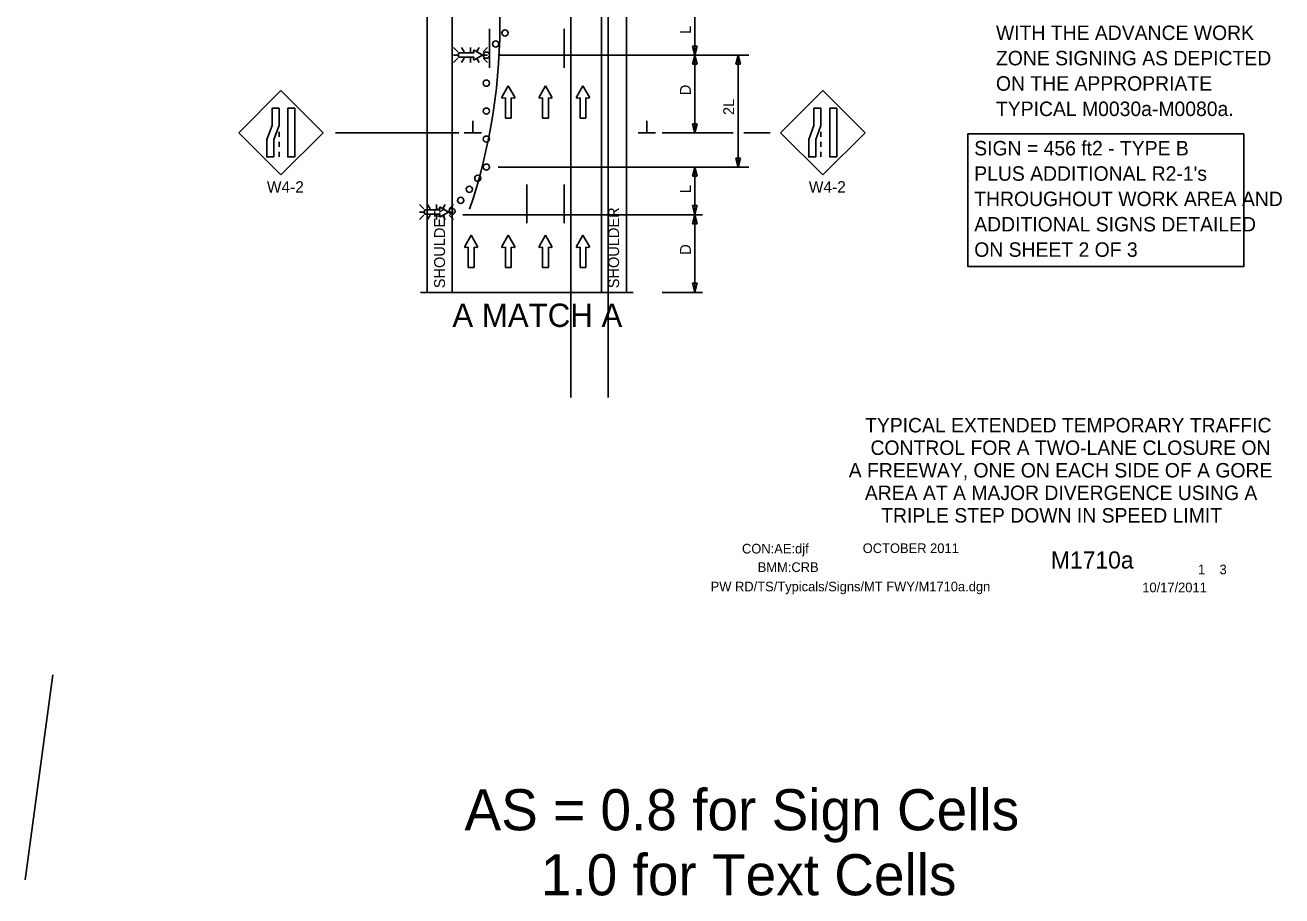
# Model space of a CAD drawing. Extents: x 16630 to 19509, y 5576 to 6998.
# Drawn here: x 16630 to 17438, y 5738 to 6298 of the extents above; entities that cross this region are included whole.
import ezdxf

# ---------------------------------------------------------------- set-up
doc = ezdxf.new("R2010")
doc.units = 0
for name, color, linetype in [('ALI_LEGAL_EX', 7, 'Continuous'), ('BORDER', 7, 'Continuous'), ('BORDER_SIGNAL_WO', 7, 'Continuous'), ('MT_SCRATCH_LEVEL_E', 7, 'Continuous'), ('PAVT_EDGE_EX', 7, 'Continuous'), ('TRAFFIC_SIGNS_PR', 7, 'Continuous'), ('TYPICAL_TEXT_DIMEN_EX', 7, 'Continuous'), ('TYPICAL_TEXT_DIMEN_PR', 7, 'Continuous')]:
    doc.layers.add(name, color=color, linetype=linetype)

msp = doc.modelspace()

# ---------------------------------------------------------------- linework, layer by layer
at = {"layer": 'ALI_LEGAL_EX'}
for p, q in [((16980.68, 6974.12), (16980.68, 6155.98)), ((17004.68, 6974.12), (17004.68, 6155.98)), ((16980.68, 6922.21), (16980.68, 6058.3)), ((17004.68, 6922.21), (17004.68, 6058.3))]:
    msp.add_line(p, q, dxfattribs=at)
for points in [[(16928.4, 6270.33), (16928.4, 6295.33)], [(16976.4, 6270.33), (16976.4, 6295.33)], [(16952.4, 6170.33), (16952.4, 6195.33)], [(16976.4, 6170.33), (16976.4, 6195.33)]]:
    msp.add_lwpolyline(points, dxfattribs=at)
msp.add_arc((16571.06, 6296.99), 364, 341.14744, 21.33821, dxfattribs=at)
at = {"layer": 'MT_SCRATCH_LEVEL_E'}
for p, q in [((16940.5, 6258.7), (16936.39, 6251.46)), ((16944.64, 6251.46), (16940.5, 6258.7)), ((16964.4, 6258.7), (16960.29, 6251.46)), ((16968.55, 6251.46), (16964.4, 6258.7)), ((16988.45, 6258.7), (16984.34, 6251.46)), ((16992.6, 6251.46), (16988.45, 6258.7)), ((16936.87, 6250.78), (16938.64, 6251.09)), ((16938.64, 6251.09), (16938.64, 6237.84)), ((16942.39, 6237.84), (16942.39, 6251.09)), ((16942.39, 6251.09), (16944.16, 6250.78)), ((16960.77, 6250.78), (16962.55, 6251.09)), ((16962.55, 6251.09), (16962.55, 6237.84)), ((16966.29, 6237.84), (16966.29, 6251.09)), ((16966.29, 6251.09), (16968.07, 6250.78)), ((16984.82, 6250.78), (16986.6, 6251.09)), ((16986.6, 6251.09), (16986.6, 6237.84)), ((16990.34, 6237.84), (16990.34, 6251.09)), ((16990.34, 6251.09), (16992.12, 6250.78)), ((16938.64, 6237.84), (16942.39, 6237.84)), ((16962.55, 6237.84), (16966.29, 6237.84)), ((16986.6, 6237.84), (16990.34, 6237.84)), ((16916.59, 6162.72), (16912.48, 6155.48)), ((16920.74, 6155.48), (16916.59, 6162.72)), ((16940.5, 6162.72), (16936.39, 6155.48)), ((16944.64, 6155.48), (16940.5, 6162.72)), ((16964.4, 6162.72), (16960.29, 6155.48)), ((16968.55, 6155.48), (16964.4, 6162.72)), ((16988.45, 6162.72), (16984.34, 6155.48)), ((16992.6, 6155.48), (16988.45, 6162.72)), ((16912.96, 6154.79), (16914.74, 6155.11)), ((16914.74, 6155.11), (16914.74, 6141.85)), ((16918.48, 6141.85), (16918.48, 6155.11)), ((16918.48, 6155.11), (16920.26, 6154.79)), ((16936.87, 6154.79), (16938.64, 6155.11)), ((16938.64, 6155.11), (16938.64, 6141.85)), ((16942.39, 6141.85), (16942.39, 6155.11)), ((16942.39, 6155.11), (16944.16, 6154.79)), ((16960.77, 6154.79), (16962.55, 6155.11)), ((16962.55, 6155.11), (16962.55, 6141.85)), ((16966.29, 6141.85), (16966.29, 6155.11)), ((16966.29, 6155.11), (16968.07, 6154.79)), ((16984.82, 6154.79), (16986.6, 6155.11)), ((16986.6, 6155.11), (16986.6, 6141.85)), ((16990.34, 6141.85), (16990.34, 6155.11)), ((16990.34, 6155.11), (16992.12, 6154.79)), ((16914.74, 6141.85), (16918.48, 6141.85)), ((16938.64, 6141.85), (16942.39, 6141.85)), ((16962.55, 6141.85), (16966.29, 6141.85)), ((16986.6, 6141.85), (16990.34, 6141.85))]:
    msp.add_line(p, q, dxfattribs=at)
for centre, start, end in [((16936.79, 6251.24), 150.42484, 279.96381), ((16944.23, 6251.24), 260.03619, 29.77312), ((16960.7, 6251.24), 150.42484, 279.96381), ((16968.14, 6251.24), 260.03619, 29.77312), ((16984.75, 6251.24), 150.42484, 279.96381), ((16992.19, 6251.24), 260.03619, 29.77312), ((16912.89, 6155.25), 150.42484, 279.96381), ((16920.33, 6155.25), 260.03619, 29.77312), ((16936.79, 6155.25), 150.42484, 279.96381), ((16944.23, 6155.25), 260.03619, 29.77312), ((16960.7, 6155.25), 150.42484, 279.96381), ((16968.14, 6155.25), 260.03619, 29.77312), ((16984.75, 6155.25), 150.42484, 279.96381), ((16992.19, 6155.25), 260.03619, 29.77312)]:
    msp.add_arc(centre, 0.463, start, end, dxfattribs=at)
at = {"layer": 'PAVT_EDGE_EX'}
for p, q in [((16888.4, 6480.53), (16888.4, 6125.9)), ((16904.4, 6480.53), (16904.4, 6125.9)), ((17000.4, 6480.53), (17000.4, 6125.9)), ((17016.4, 6480.53), (17016.4, 6125.9))]:
    msp.add_line(p, q, dxfattribs=at)
at = {"layer": 'TRAFFIC_SIGNS_PR'}
for p, q in [((16908.17, 6280.57), (16905.35, 6283.39)), ((16908.17, 6278.54), (16905.35, 6278.54)), ((16908.17, 6276.51), (16905.35, 6273.69)), ((16910.47, 6283.39), (16912.1, 6280.57)), ((16912.12, 6276.51), (16910.5, 6273.69)), ((16916.26, 6280.57), (16916.26, 6283.39)), ((16916.26, 6276.51), (16916.26, 6273.69)), ((16920.44, 6275.87), (16921.7, 6273.69)), ((16921.73, 6283.39), (16920.52, 6281.3)), ((16927.16, 6283.39), (16924.35, 6280.57)), ((16924.35, 6278.54), (16927.16, 6278.54)), ((16927.16, 6273.69), (16924.35, 6276.51)), ((16794.4, 6255.74), (16767.24, 6228.58)), ((16821.55, 6228.58), (16794.4, 6255.74)), ((17142.7, 6255.74), (17115.54, 6228.58)), ((17169.85, 6228.58), (17142.7, 6255.74)), ((16767.24, 6228.58), (16794.4, 6201.43)), ((16793.15, 6229.07), (16793.15, 6225.87)), ((16794.4, 6201.43), (16821.55, 6228.58)), ((17115.54, 6228.58), (17142.7, 6201.43)), ((17141.45, 6229.07), (17141.45, 6225.87)), ((17142.7, 6201.43), (17169.85, 6228.58)), ((16793.15, 6222.67), (16793.15, 6219.47)), ((17141.45, 6222.67), (17141.45, 6219.47)), ((16793.15, 6216.27), (16793.15, 6213.07)), ((17141.45, 6216.27), (17141.45, 6213.07)), ((16886.3, 6179.62), (16883.48, 6182.44)), ((16888.6, 6182.44), (16890.23, 6179.62)), ((16894.39, 6179.62), (16894.39, 6182.44)), ((16899.86, 6182.44), (16898.65, 6180.35)), ((16905.29, 6182.44), (16902.47, 6179.62)), ((16886.3, 6177.59), (16883.48, 6177.59)), ((16886.3, 6175.56), (16883.48, 6172.74)), ((16890.25, 6175.56), (16888.62, 6172.74)), ((16894.39, 6175.56), (16894.39, 6172.74)), ((16898.57, 6174.92), (16899.83, 6172.74)), ((16902.47, 6177.59), (16905.29, 6177.59)), ((16905.29, 6172.74), (16902.47, 6175.56))]:
    msp.add_line(p, q, dxfattribs=at)
for points in [[(16918.09, 6281.22), (16918.32, 6279.93), (16908.59, 6279.93), (16908.59, 6277.18), (16918.32, 6277.18), (16918.08, 6275.88)], [(16918.59, 6275.53), (16923.9, 6278.54), (16918.59, 6281.58)], [(16896.21, 6180.27), (16896.44, 6178.97), (16886.72, 6178.97), (16886.72, 6176.23), (16896.44, 6176.23), (16896.21, 6174.93)], [(16896.71, 6174.57), (16902.02, 6177.59), (16896.71, 6180.63)]]:
    msp.add_lwpolyline(points, dxfattribs=at)
for points in [[(16793.15, 6244.32), (16793.15, 6233.14), (16789.81, 6224.26), (16789.81, 6213.07), (16785.31, 6213.07), (16785.31, 6224.26), (16788.66, 6233.14), (16788.66, 6244.32)], [(16803.29, 6244.32), (16803.29, 6213.07), (16798.79, 6213.07), (16798.79, 6244.32)], [(17141.45, 6244.32), (17141.45, 6233.14), (17138.1, 6224.26), (17138.1, 6213.07), (17133.61, 6213.07), (17133.61, 6224.26), (17136.95, 6233.14), (17136.95, 6244.32)], [(17151.58, 6244.32), (17151.58, 6213.07), (17147.09, 6213.07), (17147.09, 6244.32)]]:
    msp.add_lwpolyline(points, close=True, dxfattribs=at)
for centre in [(16938.4, 6292.75), (16932.4, 6285.61), (16926.4, 6278.47), (16926.4, 6260.47), (16926.4, 6242.47), (16926.4, 6224.47), (16926.4, 6206.47), (16920.9, 6199.34), (16909.91, 6185.08), (16915.4, 6192.21), (16904.41, 6177.96)]:
    msp.add_circle(centre, 2, dxfattribs=at)
for centre, start, end in [((16918.42, 6281.28), 61.48329, 189.95933), ((16918.42, 6275.82), 170.73078, 298.89165), ((16896.55, 6180.33), 61.48329, 189.95933), ((16896.55, 6174.87), 170.73078, 298.89165)]:
    msp.add_arc(centre, 0.341, start, end, dxfattribs=at)
at = {"layer": 'TYPICAL_TEXT_DIMEN_EX'}
msp.add_lwpolyline([(17235.9, 6227.83), (17413.17, 6227.83), (17413.17, 6142.51), (17235.9, 6142.51)], close=True, dxfattribs=at)
at = {"layer": 'TYPICAL_TEXT_DIMEN_PR'}
for p, q in [((17060.4, 6278.47), (17060.4, 6307.03)), ((17060.4, 6278.47), (17058.83, 6284.33)), ((17058.83, 6284.33), (17060.4, 6284.33)), ((17060.4, 6284.33), (17061.97, 6284.33)), ((17061.97, 6284.33), (17060.4, 6278.47)), ((17095.19, 6278.47), (16933.9, 6278.47)), ((17058.83, 6272.61), (17060.4, 6278.47)), ((17060.4, 6278.47), (17060.4, 6228.47)), ((17060.4, 6278.47), (17061.97, 6272.61)), ((17086.64, 6272.61), (17088.21, 6278.47)), ((17088.21, 6278.47), (17089.78, 6272.61)), ((17088.21, 6278.47), (17088.21, 6206.47)), ((17060.4, 6272.61), (17058.83, 6272.61)), ((17061.97, 6272.61), (17060.4, 6272.61)), ((17088.21, 6272.61), (17086.64, 6272.61)), ((17089.78, 6272.61), (17088.21, 6272.61)), ((16917.69, 6228.47), (16917.69, 6236.25)), ((17029.53, 6228.47), (17029.53, 6236.25)), ((16829.5, 6228.47), (16908.69, 6228.47)), ((16923.31, 6228.47), (16912.06, 6228.47)), ((17035.15, 6228.47), (17023.9, 6228.47)), ((17084.97, 6228.47), (17039.4, 6228.47)), ((17060.4, 6228.47), (17058.83, 6234.33)), ((17058.83, 6234.33), (17060.4, 6234.33)), ((17060.4, 6234.33), (17061.97, 6234.33)), ((17061.97, 6234.33), (17060.4, 6228.47)), ((17108.81, 6228.47), (17091.83, 6228.47)), ((17088.21, 6206.47), (17086.64, 6212.33)), ((17086.64, 6212.33), (17088.21, 6212.33)), ((17088.21, 6212.33), (17089.78, 6212.33)), ((17089.78, 6212.33), (17088.21, 6206.47)), ((16933.9, 6206.47), (17095.19, 6206.47)), ((17058.83, 6200.61), (17060.4, 6206.47)), ((17060.4, 6175.9), (17060.4, 6206.47)), ((17060.4, 6206.47), (17061.97, 6200.61)), ((17060.4, 6200.61), (17058.83, 6200.61)), ((17061.97, 6200.61), (17060.4, 6200.61)), ((17060.4, 6175.9), (17058.83, 6181.77)), ((17058.83, 6181.77), (17060.4, 6181.77)), ((17060.4, 6181.77), (17061.97, 6181.77)), ((17061.97, 6181.77), (17060.4, 6175.9)), ((16911.36, 6175.9), (17065.4, 6175.9)), ((17058.83, 6170.04), (17060.4, 6175.9)), ((17060.4, 6175.9), (17060.4, 6125.9)), ((17060.4, 6175.9), (17061.97, 6170.04)), ((17060.4, 6170.04), (17058.83, 6170.04)), ((17061.97, 6170.04), (17060.4, 6170.04)), ((17060.4, 6125.9), (17058.83, 6131.77)), ((17058.83, 6131.77), (17060.4, 6131.77)), ((17060.4, 6131.77), (17061.97, 6131.77)), ((17061.97, 6131.77), (17060.4, 6125.9)), ((16884.1, 6125.9), (17020.75, 6125.9)), ((17065.4, 6125.9), (17039.4, 6125.9)), ((16647.75, 5880), (16629.99, 5748.32))]:
    msp.add_line(p, q, dxfattribs=at)

# ---------------------------------------------------------------- texts
at = {"layer": 'BORDER'}
for s, p in [('TYPICAL EXTENDED TEMPORARY TRAFFIC', (17169.79, 6035.9)), ('CONTROL FOR A TWO-LANE CLOSURE ON', (17173.28, 6021.41)), ('A FREEWAY, ONE ON EACH SIDE OF A GORE', (17159.3, 6006.92)), ('AREA AT A MAJOR DIVERGENCE USING A', (17169.66, 5992.42)), ('TRIPLE STEP DOWN IN SPEED LIMIT', (17180.16, 5977.93))]:
    msp.add_text(s, height=9.3, dxfattribs=at).set_placement(p)
at = {"layer": 'BORDER_SIGNAL_WO'}
for s, height, p in [('CON:AE:djf  ', 6.2, (17090.69, 5958.06)), ('    OCTOBER 2011', 6.2, (17159.08, 5958.34)), ('BMM:CRB', 6.2, (17100.81, 5946.17)), ('    M1710a   ', 11, (17272.86, 5948.38)), (' 1    3 ', 6.2, (17381.45, 5944.7)), ('PW RD/TS/Typicals/Signs/MT FWY/M1710a.dgn      ', 6.2, (17070.55, 5933.71)), ('10/17/2011', 6.2, (17347.93, 5933.13)), ('AS = 0.8 for Sign Cells', 26.4241, (16912.35, 5780.08)), ('     1.0 for Text Cells', 26.4241, (16912.35, 5738.29))]:
    msp.add_text(s, height=height, dxfattribs=at).set_placement(p)
at = {"layer": 'TRAFFIC_SIGNS_PR'}
for p in [(16785.35, 6189.99), (17133.65, 6189.99)]:
    msp.add_text('W4-2', height=7.44, dxfattribs=at).set_placement(p)
at = {"layer": 'TYPICAL_TEXT_DIMEN_EX'}
for s, p in [('WITH THE ADVANCE WORK', (17253.92, 6288.21)), ('ZONE SIGNING AS DEPICTED', (17253.92, 6271.91)), ('ON THE APPROPRIATE', (17253.92, 6255.61)), ('TYPICAL M0030a-M0080a.', (17253.92, 6239.31)), ('SIGN = 456 ft2 - TYPE B', (17239.95, 6214)), ("PLUS ADDITIONAL R2-1's", (17239.95, 6197.7)), ('THROUGHOUT WORK AREA AND', (17239.95, 6181.4)), ('ADDITIONAL SIGNS DETAILED', (17239.95, 6165.1)), ('ON SHEET 2 OF 3', (17239.95, 6148.8))]:
    msp.add_text(s, height=9.3, dxfattribs=at).set_placement(p)
at = {"layer": 'TYPICAL_TEXT_DIMEN_PR'}
for s, p in [('L', (17057.93, 6292.11)), ('D', (17057.84, 6252.69)), ('2L', (17085.65, 6239.97)), ('L', (17057.84, 6189.76)), ('SHOULDER', (16899.84, 6128.61)), ('SHOULDER', (17011.7, 6128.61)), ('D', (17057.84, 6150.12))]:
    msp.add_text(s, height=7, rotation=90, dxfattribs=at).set_placement(p)
msp.add_text('A MATCH A', height=15, dxfattribs=at).set_placement((16904.56, 6103.71))

doc.saveas('drawing.dxf')
